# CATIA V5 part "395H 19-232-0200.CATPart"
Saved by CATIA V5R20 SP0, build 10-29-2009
Part number: 395H 19-232-0200
Source: Unknown
Bounding box of the stored display mesh (mm): x -30.125 to 30.125, y -30.125 to 30.125, z -50 to 20
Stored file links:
  C:\Users\Utente\Desktop\3D files 395H FCA\395H 19-232-0200.CATPart
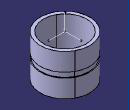
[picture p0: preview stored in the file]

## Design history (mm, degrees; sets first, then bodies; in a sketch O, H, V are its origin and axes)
Set1
  Line1 to Line3: stored without definition
  Point1 "Punto.4": stored without definition
Body1 (main body)
  Solid1 "PartBody": solid without history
